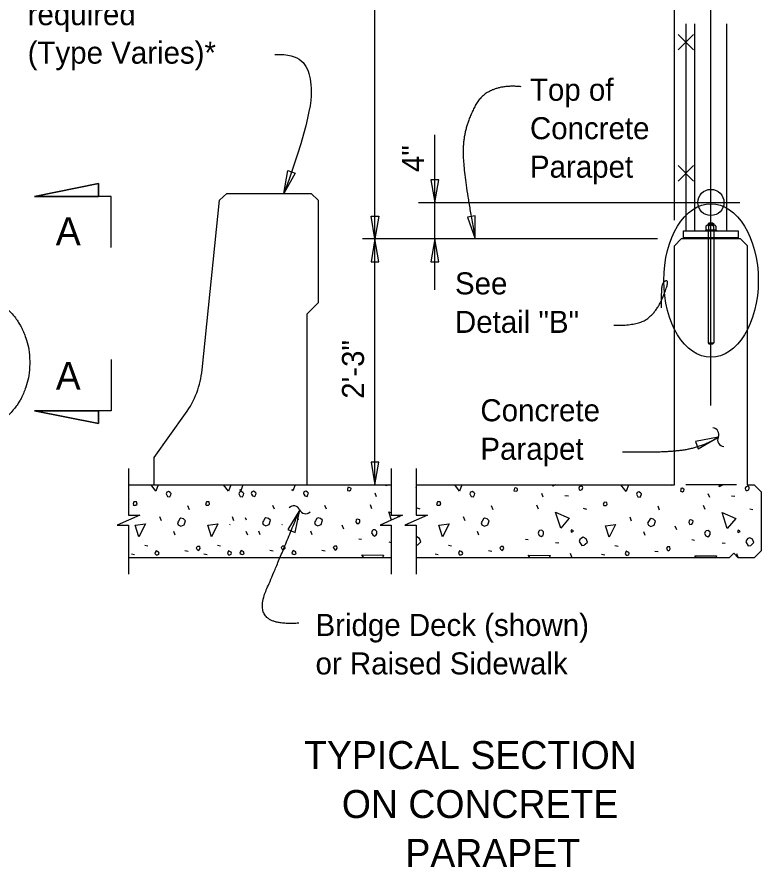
# Model space of a CAD drawing. Extents: x 0 to 41, y -96 to 25.
# Drawn here: x 33.7 to 40.51, y -85.02 to -77.25 of the extents above; entities that cross this region are included whole.
import ezdxf

# ---------------------------------------------------------------- set-up
doc = ezdxf.new("R2010")
doc.units = 0
for name, color, linetype in [('CL_Major', 7, 'Continuous'), ('Dimension', 7, 'Continuous'), ('Miscellaneous', 7, 'Continuous'), ('SteelMisc', 7, 'Continuous'), ('SteelMisc_h', 7, 'Continuous'), ('SupstrConc', 7, 'Continuous'), ('SupstrConc_h', 7, 'Continuous'), ('TextStructures', 7, 'Continuous')]:
    doc.layers.add(name, color=color, linetype=linetype)

# ---------------------------------------------------------------- blocks, each defined once
blk = doc.blocks.new('Terminator-Arrow')
at = {"layer": 'Dimension'}
blk.add_lwpolyline([(0, 0), (-0.00041, 0.000069), (-0.00041, -0.000069), (0, 0)], dxfattribs=at)
blk.add_lwpolyline([(0, 0), (-0.00041, 0.000069), (-0.00041, -0.000069)], close=True, dxfattribs=at)

msp = doc.modelspace()

# ---------------------------------------------------------------- linework, layer by layer
at = {"layer": 'CL_Major'}
for p, q in [((40.0537, -80.8047), (40.0537, -76.5853)), ((37.3776, -78.9464), (40.3194, -78.9464))]:
    msp.add_line(p, q, dxfattribs=at)
at = {"layer": 'Dimension'}
for p, q in [((36.9797, -81.5095), (36.9797, -73.2797)), ((39.7204, -79.1091), (39.7204, -77.0017)), ((37.5276, -79.7451), (37.5276, -78.3281)), ((33.8643, -78.8902), (34.4503, -78.773)), ((34.4503, -78.773), (34.4503, -78.8902)), ((34.5675, -78.8902), (33.8643, -78.8902)), ((34.5675, -79.359), (34.5675, -78.8902)), ((40.0537, -79.199), (40.0537, -79.1998)), ((39.5643, -79.2797), (36.8659, -79.2797)), ((34.5675, -80.382), (34.5675, -80.8508)), ((34.5675, -80.8508), (33.8643, -80.8508)), ((33.8643, -80.8508), (34.4503, -80.968)), ((34.4503, -80.968), (34.4503, -80.8508))]:
    msp.add_line(p, q, dxfattribs=at)
for points in [[(37.5276, -78.9464), (37.5629, -78.7381), (37.4923, -78.7381)], [(34.4503, -78.8902), (34.4503, -78.773), (33.8643, -78.8902)], [(36.9797, -79.2797), (36.9444, -79.0714), (37.015, -79.0714)], [(37.8983, -79.2797), (37.8958, -79.0685), (37.8263, -79.0811)], [(36.9797, -79.2797), (36.9444, -79.4879), (37.015, -79.4879)], [(37.5276, -79.2797), (37.4923, -79.4879), (37.5629, -79.4879)], [(34.4503, -80.8508), (34.4503, -80.968), (33.8643, -80.8508)], [(40.1214, -81.0935), (39.9139, -81.1332), (39.9386, -81.1993)], [(36.9797, -81.5297), (37.015, -81.3214), (36.9444, -81.3214)], [(36.2916, -81.7574), (36.1831, -81.9386), (36.2488, -81.9642)]]:
    msp.add_lwpolyline(points, close=True, dxfattribs=at)
for points in [[(34.7238, -81.3797), (34.7238, -81.8068), (34.8272, -81.8068), (34.7238, -81.8518), (34.6205, -81.8968), (34.7238, -81.8968), (34.7238, -82.3464)], [(37.1296, -81.3797), (37.1296, -81.8068), (37.233, -81.8068), (37.1296, -81.8518), (37.0263, -81.8968), (37.1296, -81.8968), (37.1296, -82.3464)], [(37.3569, -81.3797), (37.3569, -81.8068), (37.4602, -81.8068), (37.3569, -81.8518), (37.2536, -81.8968), (37.3569, -81.8968), (37.3569, -82.3464)]]:
    msp.add_lwpolyline(points, dxfattribs=at)
for centre, start, end in [((40.0672, -81.0673), 334.61622, 86.34344), ((40.1749, -81.1185), 154.61622, 266.34344), ((36.236, -81.7804), 22.88008, 134.6073), ((36.3458, -81.734), 202.88008, 314.6073)]:
    msp.add_arc(centre, 0.0596, start, end, dxfattribs=at)
msp.add_ellipse((40.055, -79.6599), major_axis=(0, 0.7024), ratio=0.61552, dxfattribs=at)
for points, degree in [([(36.0647, -77.5916), (36.3066, -77.5857), (36.4128, -77.7747), (36.4128, -78.1289), (36.1473, -78.863)], 3), ([(38.3183, -77.8874), (38.0045, -77.8568), (37.7862, -78.2724), (37.7862, -78.6917), (37.8983, -79.2797)], 2), ([(39.1649, -80.0697), (39.3915, -80.0737), (39.562, -79.9387), (39.6571, -79.7086), (39.6571, -79.6568), (39.6199, -79.6717), (39.5976, -79.7244), (39.599, -79.9113)], 2), ([(33.2986, -81.0268), (33.3336, -81.0268), (33.3683, -81.0226), (33.4362, -81.0065), (33.4694, -80.9945), (33.5172, -80.9709), (33.5328, -80.9621), (33.5556, -80.9476), (33.5631, -80.9425), (33.5779, -80.9319), (33.5851, -80.9264), (33.6208, -80.898), (33.6471, -80.8721), (33.695, -80.815), (33.7165, -80.7838), (33.7399, -80.7419), (33.7444, -80.7334), (33.7531, -80.7161), (33.7573, -80.7073), (33.7692, -80.6806), (33.7764, -80.6625), (33.8084, -80.5701), (33.8217, -80.491), (33.8217, -80.3307), (33.8084, -80.2516), (33.7764, -80.1592), (33.7692, -80.1411), (33.7573, -80.1145), (33.7531, -80.1057), (33.7444, -80.0884), (33.7399, -80.0799), (33.7165, -80.038), (33.695, -80.0067), (33.6471, -79.9496), (33.6208, -79.9237), (33.5851, -79.8953), (33.5779, -79.8898), (33.5631, -79.8793), (33.5556, -79.8742), (33.5328, -79.8596), (33.5172, -79.8508), (33.4694, -79.8272), (33.4362, -79.8152), (33.3683, -79.7991), (33.3336, -79.795), (33.2636, -79.795), (33.2289, -79.7991), (33.1609, -79.8152), (33.1278, -79.8272), (33.08, -79.8508), (33.0644, -79.8596), (33.0416, -79.8742), (33.0341, -79.8793), (33.0193, -79.8898), (33.0121, -79.8953), (32.9764, -79.9237), (32.9501, -79.9496), (32.9022, -80.0067), (32.8807, -80.038), (32.8573, -80.0799), (32.8527, -80.0884), (32.8441, -80.1057), (32.8399, -80.1145), (32.828, -80.1411), (32.8208, -80.1592), (32.7887, -80.2516), (32.7755, -80.3307), (32.7755, -80.491), (32.7887, -80.5701), (32.8208, -80.6625), (32.828, -80.6806), (32.8399, -80.7073), (32.8441, -80.7161), (32.8527, -80.7334), (32.8573, -80.7419), (32.8807, -80.7838), (32.9022, -80.815), (32.9501, -80.8721), (32.9764, -80.898), (33.0121, -80.9264), (33.0193, -80.9319), (33.0341, -80.9425), (33.0416, -80.9476), (33.0644, -80.9621), (33.08, -80.9709), (33.1278, -80.9945), (33.1609, -81.0065), (33.2289, -81.0226), (33.2636, -81.0268), (33.2986, -81.0268)], 3), ([(39.246, -81.2258), (39.5846, -81.2341), (39.9562, -81.1928), (40.1214, -81.0936)], 2), ([(36.2826, -82.7947), (36.0506, -82.8114), (35.9147, -82.6524), (36.0652, -82.3092), (36.2916, -81.7574)], 2)]:
    msp.add_open_spline(points, degree=degree, dxfattribs=at)
at = {"layer": 'Miscellaneous'}
for p, q in [((39.8952, -77.4091), (39.7538, -77.5503)), ((39.7538, -77.4091), (39.8952, -77.5503)), ((39.8952, -78.6091), (39.7538, -78.7503)), ((39.7538, -78.6091), (39.8952, -78.7503)), ((40.0425, -79.1374), (40.0633, -79.1374)), ((40.0425, -79.1471), (40.0633, -79.1471)), ((39.8037, -79.2728), (40.3037, -79.2728)), ((39.8037, -79.2762), (40.3037, -79.2762)), ((35.3909, -81.5297), (35.3923, -81.53)), ((38.169, -81.5297), (38.1703, -81.53)), ((39.6751, -81.5297), (39.6941, -81.5335)), ((36.9947, -81.6378), (36.9824, -81.6042)), ((38.5186, -81.6413), (38.5062, -81.6078)), ((38.7183, -81.6254), (38.7501, -81.629)), ((40.0424, -81.6449), (40.03, -81.6113)), ((40.2421, -81.629), (40.274, -81.6325)), ((36.9523, -81.7474), (36.9382, -81.7121)), ((38.4761, -81.7509), (38.462, -81.7156)), ((35.2827, -81.7562), (35.2685, -81.7209)), ((36.0602, -81.7527), (36.0461, -81.7174)), ((36.5369, -81.7527), (36.5228, -81.7174)), ((37.3624, -81.7403), (37.3907, -81.7474)), ((38.0607, -81.7562), (38.0466, -81.7209)), ((38.8863, -81.7439), (38.9145, -81.7509)), ((39.5845, -81.7598), (39.5704, -81.7244)), ((39.9999, -81.7545), (39.9858, -81.7191)), ((40.4101, -81.7474), (40.4384, -81.7545)), ((35.0263, -81.857), (35.0122, -81.8217)), ((35.6898, -81.857), (35.6757, -81.8217)), ((35.8039, -81.8535), (35.7944, -81.8298)), ((36.2806, -81.8535), (36.2711, -81.8298)), ((37.8044, -81.857), (37.7902, -81.8217)), ((39.3282, -81.8605), (39.3141, -81.8252)), ((36.6942, -81.9348), (36.6801, -81.8994)), ((39.7419, -81.9419), (39.7277, -81.9065)), ((35.1519, -81.9896), (35.1395, -81.956)), ((35.8154, -81.9896), (35.803, -81.956)), ((35.9294, -81.9861), (35.917, -81.9525)), ((36.4061, -81.9861), (36.3937, -81.9525)), ((36.8321, -82.0232), (36.8569, -82.0267)), ((37.9299, -81.9896), (37.9175, -81.956)), ((39.4537, -81.9931), (39.4413, -81.9595)), ((34.8743, -82.0797), (34.9026, -82.0868)), ((35.5378, -82.0797), (35.5661, -82.0868)), ((37.1079, -82.0515), (37.1296, -82.0553)), ((37.6524, -82.0797), (37.6806, -82.0868)), ((38.3559, -82.0267), (38.3807, -82.0302)), ((38.6317, -82.055), (38.6617, -82.0603)), ((39.1762, -82.0833), (39.2045, -82.0904)), ((39.8797, -82.0302), (39.9045, -82.0338)), ((40.1555, -82.0585), (40.1856, -82.0638)), ((34.7523, -82.1593), (34.7806, -82.1664)), ((35.2402, -82.131), (35.2703, -82.1363)), ((35.4158, -82.1593), (35.4441, -82.1664)), ((36.0178, -82.1275), (36.0478, -82.1328)), ((36.4945, -82.1275), (36.5245, -82.1328)), ((37.5304, -82.1593), (37.5587, -82.1664)), ((38.0183, -82.131), (38.0483, -82.1363)), ((38.7802, -82.1893), (38.7678, -82.1558)), ((39.0542, -82.1628), (39.0825, -82.1699)), ((39.5421, -82.1345), (39.5721, -82.1398)), ((40.304, -82.1929), (40.2916, -82.1593))]:
    msp.add_line(p, q, dxfattribs=at)
for points in [[(39.8246, -77.3123), (39.8246, -79.2068)], [(34.9751, -81.5865), (34.9319, -81.5297)], [(34.9963, -81.5297), (34.9751, -81.5865)], [(35.6386, -81.5865), (35.5954, -81.5297)], [(35.6598, -81.5297), (35.6386, -81.5865)], [(35.7725, -81.5297), (35.7526, -81.583)], [(36.2492, -81.5297), (36.2293, -81.583)], [(36.7278, -81.5795), (36.7473, -81.5848), (36.7596, -81.5759), (36.7614, -81.5636), (36.7579, -81.56), (36.7437, -81.553), (36.7314, -81.5547), (36.7296, -81.5671), (36.7278, -81.5795)], [(37.0831, -81.5388), (37.0859, -81.5297)], [(37.1034, -81.5297), (37.0831, -81.5388)], [(37.3569, -81.5519), (37.3571, -81.5512), (37.3569, -81.55)], [(37.7531, -81.5865), (37.7099, -81.5297)], [(37.7744, -81.5297), (37.7531, -81.5865)], [(38.2516, -81.583), (38.2711, -81.5883), (38.2834, -81.5795), (38.2852, -81.5671), (38.2817, -81.5636), (38.2675, -81.5565), (38.2552, -81.5583), (38.2534, -81.5706), (38.2516, -81.583)], [(38.6069, -81.5423), (38.6108, -81.5297)], [(38.6351, -81.5297), (38.6069, -81.5423)], [(38.8544, -81.5777), (38.8615, -81.5777), (38.8756, -81.5706), (38.881, -81.5547), (38.8792, -81.5459), (38.865, -81.5388), (38.8474, -81.5494), (38.8438, -81.56), (38.8474, -81.5706), (38.8544, -81.5777)], [(39.2769, -81.5901), (39.231, -81.5297)], [(39.2995, -81.5297), (39.2769, -81.5901)], [(39.7754, -81.5865), (39.7949, -81.5918), (39.8073, -81.583), (39.809, -81.5706), (39.8055, -81.5671), (39.7914, -81.56), (39.779, -81.5618), (39.7772, -81.5742), (39.7754, -81.5865)], [(40.1308, -81.5459), (40.1357, -81.5297)], [(40.1668, -81.5297), (40.1308, -81.5459)], [(40.3782, -81.5812), (40.3853, -81.5812), (40.3995, -81.5742), (40.4048, -81.5583), (40.403, -81.5494), (40.3889, -81.5423), (40.3712, -81.553), (40.3676, -81.5636), (40.3712, -81.5742), (40.3782, -81.5812)], [(35.0741, -81.6184), (35.0829, -81.6343), (35.1041, -81.6378), (35.113, -81.6219), (35.1165, -81.6078), (35.1077, -81.5989), (35.0918, -81.5901), (35.0758, -81.5954), (35.0705, -81.6113), (35.0741, -81.6184)], [(35.7376, -81.6184), (35.7464, -81.6343), (35.7676, -81.6378), (35.7765, -81.6219), (35.78, -81.6078), (35.7712, -81.5989), (35.7553, -81.5901), (35.7393, -81.5954), (35.734, -81.6113), (35.7376, -81.6184)], [(35.7526, -81.583), (35.7438, -81.5714)], [(35.8516, -81.6148), (35.8605, -81.6307), (35.8817, -81.6343), (35.8905, -81.6184), (35.894, -81.6042), (35.8852, -81.5954), (35.8693, -81.5865), (35.8534, -81.5918), (35.8481, -81.6078), (35.8516, -81.6148)], [(36.2293, -81.583), (36.2205, -81.5714)], [(36.3283, -81.6148), (36.3371, -81.6307), (36.3584, -81.6343), (36.3672, -81.6184), (36.3707, -81.6042), (36.3619, -81.5954), (36.346, -81.5865), (36.3301, -81.5918), (36.3248, -81.6078), (36.3283, -81.6148)], [(37.8521, -81.6184), (37.861, -81.6343), (37.8822, -81.6378), (37.891, -81.6219), (37.8945, -81.6078), (37.8857, -81.5989), (37.8698, -81.5901), (37.8539, -81.5954), (37.8486, -81.6113), (37.8521, -81.6184)], [(39.3759, -81.6219), (39.3848, -81.6378), (39.406, -81.6413), (39.4148, -81.6254), (39.4184, -81.6113), (39.4095, -81.6024), (39.3936, -81.5936), (39.3777, -81.5989), (39.3724, -81.6148), (39.3759, -81.6219)], [(34.7718, -81.7156), (34.793, -81.7156), (34.8036, -81.705), (34.7983, -81.6855), (34.7753, -81.6838), (34.7718, -81.6944), (34.7665, -81.7032), (34.7718, -81.7156), (34.7683, -81.7121)], [(35.4353, -81.7156), (35.4565, -81.7156), (35.4671, -81.705), (35.4618, -81.6855), (35.4388, -81.6838), (35.4353, -81.6944), (35.43, -81.7032), (35.4353, -81.7156), (35.4318, -81.7121)], [(37.5498, -81.7156), (37.571, -81.7156), (37.5816, -81.705), (37.5763, -81.6855), (37.5534, -81.6838), (37.5498, -81.6944), (37.5445, -81.7032), (37.5498, -81.7156), (37.5463, -81.7121)], [(39.0736, -81.7191), (39.0949, -81.7191), (39.1055, -81.7085), (39.1002, -81.6891), (39.0772, -81.6873), (39.0736, -81.6979), (39.0683, -81.7067), (39.0736, -81.7191), (39.0701, -81.7156)], [(37.1323, -81.8507), (37.1079, -81.7757), (37.1296, -81.7852)], [(38.6794, -81.9259), (38.6317, -81.7792), (38.7572, -81.834), (38.6794, -81.9259)], [(40.2032, -81.9295), (40.1555, -81.7828), (40.281, -81.8376), (40.2032, -81.9295)], [(35.1801, -81.8941), (35.2031, -81.9065), (35.2332, -81.8941), (35.2455, -81.857), (35.2279, -81.8393), (35.2049, -81.834), (35.1943, -81.8411), (35.1819, -81.8605), (35.1731, -81.8765), (35.1801, -81.8941)], [(35.9577, -81.8906), (35.9807, -81.903), (36.0107, -81.8906), (36.0231, -81.8535), (36.0054, -81.8358), (35.9824, -81.8305), (35.9718, -81.8376), (35.9594, -81.857), (35.9506, -81.8729), (35.9577, -81.8906)], [(36.4344, -81.8906), (36.4573, -81.903), (36.4874, -81.8906), (36.4998, -81.8535), (36.4821, -81.8358), (36.4591, -81.8305), (36.4485, -81.8376), (36.4361, -81.857), (36.4273, -81.8729), (36.4344, -81.8906)], [(36.8038, -81.8676), (36.8127, -81.8835), (36.8321, -81.8818), (36.841, -81.8694), (36.8427, -81.8499), (36.8303, -81.8446), (36.8215, -81.8429), (36.8109, -81.8464), (36.8074, -81.8499), (36.8038, -81.8676)], [(37.1792, -81.8068), (37.206, -81.8185)], [(37.9582, -81.8941), (37.9812, -81.9065), (38.0112, -81.8941), (38.0236, -81.857), (38.0059, -81.8393), (37.9829, -81.834), (37.9723, -81.8411), (37.9599, -81.8605), (37.9511, -81.8765), (37.9582, -81.8941)], [(39.482, -81.8977), (39.505, -81.91), (39.535, -81.8977), (39.5474, -81.8605), (39.5297, -81.8429), (39.5067, -81.8376), (39.4961, -81.8446), (39.4838, -81.8641), (39.4749, -81.88), (39.482, -81.8977)], [(39.8515, -81.8747), (39.8603, -81.8906), (39.8797, -81.8888), (39.8886, -81.8765), (39.8903, -81.857), (39.878, -81.8517), (39.8691, -81.8499), (39.8585, -81.8535), (39.855, -81.857), (39.8515, -81.8747)], [(34.8195, -82.0037), (34.7859, -81.8994), (34.8796, -81.8871), (34.8195, -82.0037)], [(35.483, -82.0037), (35.4494, -81.8994), (35.5431, -81.8871), (35.483, -82.0037)], [(35.6532, -81.8913), (35.6503, -81.8968)], [(36.1298, -81.8913), (36.127, -81.8968)], [(36.9488, -81.9666), (36.9594, -81.9878), (36.9771, -81.9984), (36.9912, -81.9878), (36.9983, -81.9772), (36.9983, -81.956), (36.9824, -81.9401), (36.9629, -81.9419), (36.9541, -81.9507), (36.9488, -81.9666)], [(37.5976, -82.0037), (37.564, -81.8994), (37.6577, -81.8871), (37.5976, -82.0037)], [(38.4726, -81.9701), (38.4832, -81.9914), (38.5009, -82.002), (38.515, -81.9914), (38.5221, -81.9808), (38.5221, -81.9595), (38.5062, -81.9436), (38.4867, -81.9454), (38.4779, -81.9542), (38.4726, -81.9701)], [(38.7784, -81.9613), (38.7979, -81.9525), (38.7908, -81.9454), (38.7784, -81.9401), (38.7731, -81.9525), (38.7784, -81.9613)], [(39.1214, -82.0073), (39.0878, -81.903), (39.1815, -81.8906), (39.1214, -82.0073)], [(39.9964, -81.9737), (40.007, -81.9949), (40.0247, -82.0055), (40.0388, -81.9949), (40.0459, -81.9843), (40.0459, -81.9631), (40.03, -81.9472), (40.0106, -81.9489), (40.0017, -81.9578), (39.9964, -81.9737)], [(40.3022, -81.9648), (40.3217, -81.956), (40.3146, -81.9489), (40.3022, -81.9436), (40.2969, -81.956), (40.3022, -81.9648)], [(37.3569, -82.0791), (37.3713, -82.078), (37.3801, -82.0691), (37.3996, -82.0497), (37.3872, -82.0196), (37.3624, -82.0055), (37.3569, -82.0077)], [(38.8491, -82.0462), (38.8721, -82.0833), (38.8951, -82.0815), (38.9039, -82.0727), (38.9234, -82.0532), (38.911, -82.0232), (38.8863, -82.009), (38.8686, -82.0161), (38.8544, -82.0302), (38.8491, -82.0462)], [(40.3729, -82.0497), (40.3959, -82.0868), (40.4189, -82.085), (40.4277, -82.0762), (40.4472, -82.0568), (40.4348, -82.0267), (40.4101, -82.0126), (40.3924, -82.0196), (40.3782, -82.0338), (40.3729, -82.0497)], [(35.3516, -82.1186), (35.3622, -82.1292), (35.3728, -82.1222), (35.3799, -82.1116), (35.3764, -82.0939), (35.3675, -82.0921), (35.3551, -82.0939), (35.3445, -82.1045), (35.3516, -82.1186)], [(36.1292, -82.1151), (36.1398, -82.1257), (36.1504, -82.1186), (36.1574, -82.108), (36.1539, -82.0904), (36.1451, -82.0886), (36.1327, -82.0904), (36.1221, -82.101), (36.1292, -82.1151)], [(36.6058, -82.1151), (36.6164, -82.1257), (36.6271, -82.1186), (36.6341, -82.108), (36.6306, -82.0904), (36.6218, -82.0886), (36.6094, -82.0904), (36.5988, -82.101), (36.6058, -82.1151)], [(38.1297, -82.1186), (38.1403, -82.1292), (38.1509, -82.1222), (38.1579, -82.1116), (38.1544, -82.0939), (38.1456, -82.0921), (38.1332, -82.0939), (38.1226, -82.1045), (38.1297, -82.1186)], [(39.6535, -82.1222), (39.6641, -82.1328), (39.6747, -82.1257), (39.6817, -82.1151), (39.6782, -82.0974), (39.6694, -82.0957), (39.657, -82.0974), (39.6464, -82.108), (39.6535, -82.1222)], [(34.9768, -82.1681), (34.9892, -82.1699), (35.0016, -82.1646), (35.0051, -82.154), (34.9998, -82.1452), (34.9892, -82.1381), (34.9768, -82.1328), (34.9698, -82.1469), (34.9662, -82.1575), (34.9768, -82.1681)], [(35.6403, -82.1681), (35.6527, -82.1699), (35.6651, -82.1646), (35.6686, -82.154), (35.6633, -82.1452), (35.6527, -82.1381), (35.6403, -82.1328), (35.6333, -82.1469), (35.6297, -82.1575), (35.6403, -82.1681)], [(35.7544, -82.1646), (35.7668, -82.1664), (35.7791, -82.1611), (35.7827, -82.1505), (35.7774, -82.1416), (35.7668, -82.1345), (35.7544, -82.1292), (35.7473, -82.1434), (35.7438, -82.154)], [(35.7438, -82.154), (35.7544, -82.1646)], [(36.2311, -82.1646), (36.2434, -82.1664), (36.2558, -82.1611), (36.2594, -82.1505), (36.2541, -82.1416), (36.2434, -82.1345), (36.2311, -82.1292), (36.224, -82.1434), (36.2205, -82.154)], [(36.2205, -82.154), (36.2311, -82.1646)], [(36.8788, -82.1964), (36.8586, -82.1699), (37.0584, -82.1717), (37.0491, -82.1964)], [(37.7549, -82.1681), (37.7673, -82.1699), (37.7796, -82.1646), (37.7832, -82.154), (37.7779, -82.1452), (37.7673, -82.1381), (37.7549, -82.1328), (37.7478, -82.1469), (37.7443, -82.1575), (37.7549, -82.1681)], [(38.3999, -82.1964), (38.3824, -82.1734), (38.5822, -82.1752), (38.5743, -82.1964)], [(39.2787, -82.1717), (39.2911, -82.1734), (39.3034, -82.1681), (39.307, -82.1575), (39.3017, -82.1487), (39.2911, -82.1416), (39.2787, -82.1363), (39.2716, -82.1505), (39.2681, -82.1611), (39.2787, -82.1717)], [(39.921, -82.1964), (39.9063, -82.177), (40.106, -82.1787), (40.0994, -82.1964)]]:
    msp.add_lwpolyline(points, dxfattribs=at)
msp.add_lwpolyline([(39.8037, -79.2693), (40.3037, -79.2693), (40.3037, -79.2797), (39.8037, -79.2797)], close=True, dxfattribs=at)
at = {"layer": 'SteelMisc'}
for p, q in [((39.9079, -79.2068), (39.9079, -77.3123)), ((40.1996, -79.2068), (40.1996, -77.3123)), ((40.0376, -79.1325), (40.028, -79.1422)), ((40.028, -79.1422), (40.028, -79.1534)), ((40.028, -79.1422), (40.0795, -79.1422)), ((40.0376, -79.1325), (40.0682, -79.1325)), ((40.0682, -79.1325), (40.0795, -79.1422)), ((40.0795, -79.1422), (40.0795, -79.1534)), ((40.0041, -79.1998), (40.0041, -79.2069)), ((40.0041, -79.1998), (40.1035, -79.1998)), ((40.0083, -79.1621), (40.0083, -79.1998)), ((40.0991, -79.1998), (40.0083, -79.1998)), ((40.0878, -79.1534), (40.0197, -79.1534)), ((40.031, -79.1619), (40.031, -79.1998)), ((40.0764, -79.1619), (40.0764, -79.1998)), ((40.0991, -79.1621), (40.0991, -79.1998)), ((40.1035, -79.1998), (40.1035, -79.2069)), ((39.9339, -79.2693), (40.1735, -79.2693))]:
    msp.add_line(p, q, dxfattribs=at)
msp.add_lwpolyline([(39.8037, -79.2068), (40.3037, -79.2068), (40.3037, -79.2693), (39.8037, -79.2693)], close=True, dxfattribs=at)
msp.add_circle((40.0537, -78.9464), 0.1198, dxfattribs=at)
for centre, radius, start, end in [((40.0197, -79.1652), 0.0118, 16.59863, 164.70054), ((40.0537, -79.1881), 0.0347, 49.20147, 130.79853), ((40.0877, -79.1652), 0.0118, 15.15064, 163.50417)]:
    msp.add_arc(centre, radius, start, end, dxfattribs=at)
at = {"layer": 'SteelMisc_h'}
for p, q in [((40.0277, -79.2068), (40.0277, -80.2299)), ((40.0798, -79.2068), (40.0798, -80.2299)), ((40.0277, -80.2299), (40.0798, -80.2299)), ((40.0277, -80.2299), (40.0359, -80.2381)), ((40.0359, -80.2381), (40.0716, -80.2381)), ((40.0798, -80.2299), (40.0716, -80.2381))]:
    msp.add_line(p, q, dxfattribs=at)
at = {"layer": 'SupstrConc'}
for p, q in [((39.7829, -79.2797), (39.7204, -79.3431)), ((40.3245, -79.2797), (39.7829, -79.2797)), ((40.3245, -79.2797), (40.3871, -79.3431)), ((39.7204, -81.5297), (39.7204, -79.3431)), ((40.3871, -81.5297), (40.3871, -79.3431)), ((34.7238, -81.5297), (37.1296, -81.5297)), ((37.3569, -81.5297), (39.7204, -81.5297)), ((40.3871, -81.5297), (40.4496, -81.5297)), ((40.4496, -81.5297), (40.5121, -81.5922)), ((40.5121, -81.5922), (40.5121, -82.1339)), ((40.2204, -82.1964), (40.2621, -82.1547)), ((40.2621, -82.1547), (40.3037, -82.1964)), ((40.5121, -82.1339), (40.4496, -82.1964)), ((40.2204, -82.1964), (37.3569, -82.1964)), ((40.4496, -82.1964), (40.3037, -82.1964))]:
    msp.add_line(p, q, dxfattribs=at)
at = {"layer": 'SupstrConc_h'}
for p, q in [((35.5573, -78.9253), (35.6261, -78.8631)), ((35.6262, -78.863), (36.397, -78.863)), ((36.397, -78.8631), (36.4595, -78.9256)), ((35.3986, -80.4766), (35.5573, -78.9253)), ((36.4595, -78.9256), (36.4595, -79.8631)), ((36.4595, -79.8631), (36.3553, -79.9672)), ((36.3553, -79.9672), (36.3553, -81.5297)), ((34.9595, -81.2797), (35.2477, -80.8761)), ((34.9595, -81.5297), (34.9595, -81.2797)), ((40.2885, -81.5297), (39.8234, -81.5297)), ((37.1296, -82.1964), (34.7238, -82.1964))]:
    msp.add_line(p, q, dxfattribs=at)
msp.add_arc((34.5696, -80.392), 0.8333, 324.46232, 354.16034, dxfattribs=at)

# ---------------------------------------------------------------- block references
at = {"layer": 'Dimension', "xscale": 507.9999699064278, "yscale": -507.99996990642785, "rotation": -109.44616743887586}
msp.add_blockref('Terminator-Arrow', (36.1473, -78.863), dxfattribs=at)

# ---------------------------------------------------------------- texts
at = {"layer": 'Dimension'}
for s, height, p in [('required', 0.2016, (33.8024, -77.3246)), ('(Type Varies)*', 0.2016, (33.8024, -77.6766)), ('Top of ', 0.2016, (38.3979, -78.0155)), ('Concrete', 0.2016, (38.3979, -78.3675)), ('Parapet', 0.2016, (38.3979, -78.7195)), ('See ', 0.2016, (37.7119, -79.787)), ('Detail "B"', 0.2016, (37.7119, -80.139)), ('Concrete', 0.2016, (37.9448, -80.9478)), ('Parapet', 0.2016, (37.9448, -81.2998)), ('Bridge Deck (shown)', 0.2016, (36.4361, -82.9114)), ('or Raised Sidewalk', 0.2016, (36.4361, -83.2634)), ('TYPICAL SECTION', 0.256001, (36.3315, -84.1287)), ('ON CONCRETE', 0.256001, (36.6769, -84.5767)), ('PARAPET', 0.256, (37.2584, -85.0247))]:
    msp.add_text(s, height=height, dxfattribs=at).set_placement(p)
at = {"layer": 'TextStructures'}
for s, p in [('4"', (37.4279, -78.6679)), ('2\'-3"', (36.8797, -80.7416))]:
    msp.add_text(s, height=0.2016, rotation=90, dxfattribs=at).set_placement(p)
for p in [(34.0596, -79.3369), (34.0596, -80.6599)]:
    msp.add_text('A', height=0.256, dxfattribs=at).set_placement(p)

doc.saveas('drawing.dxf')
